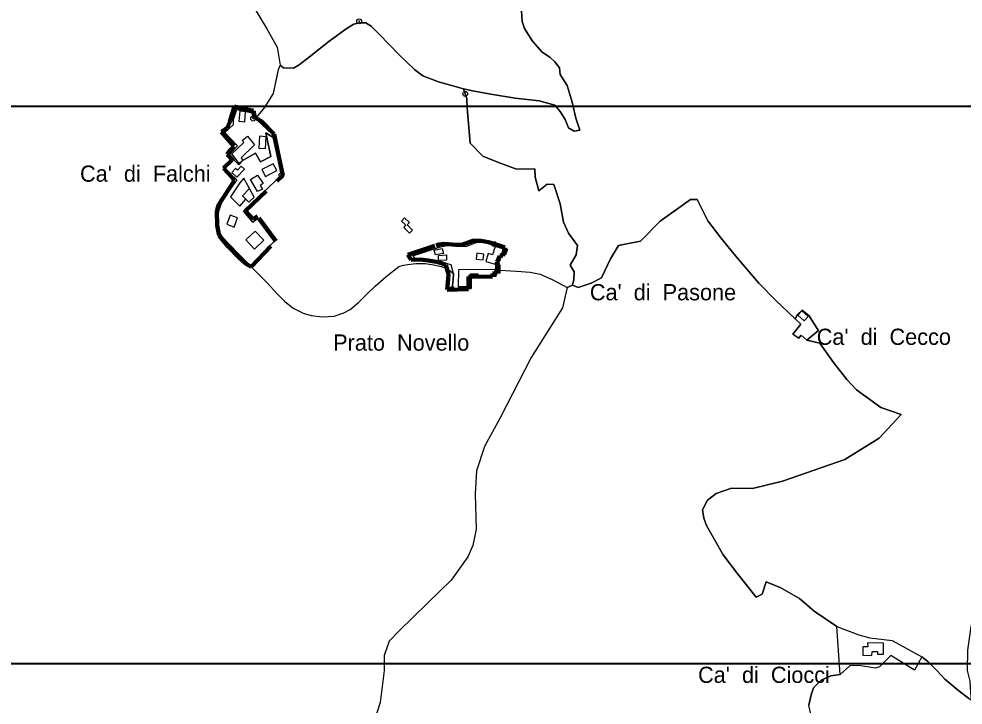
# Model space of a CAD drawing. Extents: x 645880 to 658994, y 884400 to 894744.
# Drawn here: x 652403 to 653394, y 888960 to 889680 of the extents above; entities that cross this region are included whole.
import ezdxf
from ezdxf.enums import TextEntityAlignment as Align

# ---------------------------------------------------------------- set-up
doc = ezdxf.new("R2010")
doc.units = 0
doc.header["$LTSCALE"] = 10
doc.header["$PDMODE"] = 32
doc.header["$PDSIZE"] = 5
doc.linetypes.add('MEDIUM_DASHED', pattern=[4.5, 3, -1.5])
for name, color, linetype, lineweight in [('1', 7, 'Continuous', 25), ('15', 7, 'MEDIUM_DASHED', 100), ('17', 7, 'Continuous', 25), ('18', 7, 'Continuous', 25), ('2', 7, 'Continuous', 25), ('4', 7, 'Continuous', 25), ('6', 7, 'Continuous', 25), ('62', 7, 'Continuous', 35), ('63', 7, 'Continuous', 35), ('7', 7, 'Continuous', 25), ('8', 7, 'Continuous', 25)]:
    doc.layers.add(name, color=color, linetype=linetype, lineweight=lineweight)
doc.layers.add('60', color=7, linetype='Continuous')

msp = doc.modelspace()

# ---------------------------------------------------------------- linework, layer by layer
at = {"layer": '1'}
for points in [[(652858.95, 889412.63), (652856.49, 889421.71), (652853.93, 889422.65), (652847.38, 889424.7), (652839.18, 889426.87), (652829.46, 889428.08), (652819.38, 889428.08), (652816.39, 889431.38), (652844.32, 889440.3), (652851.77, 889442.15), (652864.95, 889441.48), (652871.89, 889441.14), (652883.73, 889445.5), (652890.91, 889445.51), (652901.65, 889443.54)], [(652901.65, 889443.54), (652909.07, 889440.08), (652915.62, 889438.33), (652913.47, 889432.13), (652909.69, 889432.71), (652906.66, 889423.99), (652907.74, 889421.06)], [(652907.74, 889421.06), (652907.78, 889416.09), (652907.76, 889412.93), (652903.09, 889413.24), (652903.37, 889409.66), (652877.57, 889410.31), (652877.65, 889396.95), (652857.6, 889396.39)], [(652857.6, 889396.39), (652858.57, 889406.67), (652858.95, 889412.63)]]:
    msp.add_lwpolyline(points, dxfattribs=at)
for points in [[(652847.26, 889438.79), (652848.65, 889433.74), (652840.32, 889432.39), (652838.94, 889437.1)], [(652895.31, 889433.55), (652892.92, 889425.34), (652905.35, 889421.79), (652908.78, 889433.75), (652913.67, 889432.5), (652915.07, 889437.1), (652902.81, 889441.1), (652899.82, 889432.24)], [(652843.5, 889431.77), (652851.63, 889432.15), (652851.84, 889426.67), (652843.39, 889426.45)], [(652890.86, 889432.86), (652883.47, 889433.97), (652882.84, 889427.67), (652890.23, 889426.94)], [(652864.25, 889398.74), (652864.49, 889416.84), (652902.47, 889417.17), (652902.41, 889410.66), (652885.06, 889410.66), (652885.05, 889411.93), (652876.55, 889411.93), (652876.39, 889398.58)]]:
    msp.add_lwpolyline(points, close=True, dxfattribs=at)
for p in [(652901.65, 889443.54), (652857.6, 889396.39)]:
    msp.add_point(p, dxfattribs=at)
at = {"layer": '15'}
for points in [[(652615.75, 889561.15), (652628.62, 889546.19), (652625.49, 889542.71), (652621.66, 889537.49), (652626.89, 889531.86), (652617.68, 889523.26), (652627.35, 889513.02), (652629.14, 889510.36), (652613.02, 889485.15), (652610.93, 889478.21), (652611.13, 889463.06), (652613.38, 889452.42), (652622.59, 889440.95), (652634.46, 889428.87), (652640.8, 889423.35), (652646.74, 889419.66), (652672.79, 889446.66), (652653.45, 889472.83), (652648.79, 889469.63), (652640.9, 889478.51), (652679.89, 889515.48), (652674.55, 889541.7), (652671.05, 889558.72), (652657.84, 889572.29), (652650.53, 889576.46), (652649.14, 889583.42), (652629.32, 889587.95)], [(652629.32, 889587.95), (652626.88, 889579.94), (652624.42, 889571.91), (652621.64, 889565.6), (652615.75, 889561.15)]]:
    msp.add_lwpolyline(points, dxfattribs=at)
msp.add_lwpolyline([(652853.85, 889412.05), (652851.15, 889421.42), (652849.15, 889422.68), (652842.97, 889424.44), (652832.59, 889426.49), (652824.57, 889427.5), (652814.68, 889427.12), (652811.18, 889432.24), (652840.83, 889442.1), (652843.63, 889442.96), (652848.83, 889443.97), (652853.65, 889443.54), (652861.5, 889442.93), (652867.64, 889442.8), (652880.39, 889447.31), (652888.26, 889447.12), (652895.76, 889445.43), (652907.95, 889441.68), (652913.01, 889439.99), (652910.88, 889430.94), (652907.27, 889431.09), (652904.45, 889424.81), (652904.98, 889420.95), (652904.85, 889412.92), (652900.07, 889412.61), (652899.92, 889409.08), (652874.77, 889409.61), (652874.77, 889396.29), (652852.49, 889395.74), (652852.78, 889399.31), (652853.47, 889407.11)], close=True, dxfattribs=at)
at = {"layer": '17'}
for points in [[(652871.38, 889601.15), (652869.68, 889606.46), (652869.69, 889606.47), (652869.68, 889606.47), (652843.41, 889613.68), (652827.05, 889619.99), (652818.65, 889626.15), (652801.55, 889642.43), (652781.13, 889663.7), (652772.57, 889672.11), (652767.02, 889675.72), (652760.42, 889675.72), (652754.56, 889674.21), (652746.46, 889669.26), (652728.3, 889655.89), (652708.03, 889639.82)], [(652708.03, 889639.82), (652697.08, 889631.56), (652691.07, 889628.11), (652680.87, 889628.56), (652677.13, 889631.26), (652675.18, 889626.47), (652674.2, 889621.82)], [(652674.2, 889621.82), (652669.91, 889601.42), (652660.54, 889586.47), (652651.98, 889576.46), (652653, 889573.44), (652668.8, 889558.95), (652669.92, 889555.18), (652678.53, 889515.99), (652638.67, 889478.15), (652648.7, 889466.42), (652653.59, 889470.35), (652671.65, 889446.86), (652649.47, 889424.75)], [(652983.82, 889400.47), (652985.34, 889406.55), (652985.79, 889414.56), (652981.36, 889421.53), (652987.69, 889432.29), (652989.12, 889441.95), (652979.78, 889455.1), (652974.37, 889466.51), (652970.99, 889485.94), (652964.24, 889506.2), (652957.46, 889506.25), (652948.44, 889499.28), (652944.84, 889513.81), (652944.48, 889522.4), (652925.33, 889522.24), (652906.34, 889529.05), (652890, 889535.76), (652876.43, 889549.32), (652873.26, 889586.38), (652873.12, 889595.73), (652871.38, 889601.15)], [(652819.38, 889428.08), (652816.39, 889431.38), (652844.32, 889440.3), (652851.77, 889442.15), (652864.95, 889441.48), (652871.89, 889441.14), (652883.73, 889445.5), (652890.9, 889445.5), (652901.65, 889443.54), (652909.07, 889440.08), (652915.62, 889438.33), (652913.47, 889432.13), (652909.17, 889433.44), (652906.66, 889423.99), (652907.75, 889421.07), (652907.74, 889421.06), (652907.78, 889416.09), (652925.28, 889415.2), (652939.56, 889414.27), (652949.86, 889412.16), (652963.2, 889406.07), (652978.31, 889398.07), (652983.82, 889400.47)], [(652858.95, 889412.63), (652856.49, 889421.71), (652853.93, 889422.65), (652847.38, 889424.7), (652839.18, 889426.87), (652829.46, 889428.08), (652819.38, 889428.08)], [(652649.47, 889424.75), (652645.94, 889420.69), (652649.89, 889416.69), (652663.41, 889403), (652673.71, 889391.69), (652681.77, 889383.55), (652690.87, 889376.23), (652701.18, 889371.17), (652709.89, 889368.65), (652721.31, 889367.3), (652733.88, 889368.07), (652743.94, 889371.56), (652750.52, 889375.04), (652759.23, 889382.21), (652768.52, 889391.31), (652777.03, 889399.44), (652788.24, 889409.11), (652796.85, 889416.33), (652801.74, 889420.17), (652806.63, 889421.53), (652811.05, 889422.2), (652819.66, 889423.11), (652829.2, 889423.11), (652838.28, 889421.98), (652845.96, 889419.95), (652852.47, 889417.91), (652858.95, 889412.63)]]:
    msp.add_lwpolyline(points, dxfattribs=at)
msp.add_point((652871.38, 889601.15), dxfattribs=at)
at = {"layer": '18'}
for points in [[(652650.6, 889690.43), (652663.31, 889669.23), (652673.91, 889650.15), (652677.13, 889631.26)], [(652650.6, 889690.43), (652663.31, 889669.23), (652673.91, 889650.15), (652677.13, 889631.26)], [(652930.34, 889688.25), (652931.1, 889676.92), (652933.45, 889669.69), (652942.07, 889656.52), (652952.06, 889644.7), (652960.23, 889639.71), (652965.23, 889634.71), (652970.22, 889628.35), (652971.13, 889621.53), (652978.39, 889609.72), (652983.39, 889592.46), (652987.47, 889575.65), (652991.56, 889562.93), (652985.66, 889562.02), (652979.75, 889565.65), (652976.12, 889574.29), (652971.13, 889582.46), (652965.23, 889589.28), (652948.88, 889593.82), (652923.91, 889596.55), (652898.11, 889600.63), (652880.79, 889603.82), (652869.68, 889606.47), (652873.12, 889595.73)], [(652931.1, 889676.92), (652930.34, 889688.25)], [(652691.07, 889628.11), (652697.08, 889631.56), (652708.03, 889639.82), (652728.3, 889655.89), (652746.46, 889669.26), (652754.56, 889674.21), (652760.42, 889675.72), (652767.02, 889675.72), (652772.57, 889672.11), (652781.13, 889663.7), (652801.55, 889642.43), (652818.65, 889626.15), (652827.05, 889619.99), (652843.41, 889613.68), (652869.68, 889606.47)], [(652869.68, 889606.47), (652880.79, 889603.82), (652898.11, 889600.63), (652923.91, 889596.55), (652948.88, 889593.82), (652965.23, 889589.28), (652971.13, 889582.46), (652976.12, 889574.29), (652979.75, 889565.65), (652985.66, 889562.02), (652991.56, 889562.93), (652987.47, 889575.65), (652983.39, 889592.46), (652978.39, 889609.72), (652971.13, 889621.53), (652970.22, 889628.35), (652965.23, 889634.71), (652960.23, 889639.71), (652952.06, 889644.7), (652942.07, 889656.52), (652933.45, 889669.69), (652931.1, 889676.92)], [(652677.13, 889631.26), (652675.18, 889626.47), (652669.91, 889601.42), (652660.54, 889586.47), (652651.98, 889576.46)], [(652677.13, 889631.26), (652680.87, 889628.56), (652691.07, 889628.11)], [(652873.12, 889595.73), (652873.26, 889586.38), (652876.43, 889549.33), (652890, 889535.76), (652906.34, 889529.05), (652925.33, 889522.24), (652944.48, 889522.4), (652944.84, 889513.81), (652948.44, 889499.28), (652957.46, 889506.25), (652964.24, 889506.2), (652970.99, 889485.94), (652974.37, 889466.51), (652979.78, 889455.1), (652989.11, 889441.96)], [(652631.56, 889584.54), (652627.98, 889573.82), (652627.95, 889568.57), (652619.04, 889560.52), (652632.31, 889546.71), (652624.22, 889537.49), (652628.21, 889532.53), (652619.05, 889522.88), (652631.67, 889510.78), (652620.54, 889495.05), (652615.42, 889486.01), (652612.39, 889477.89), (652611.93, 889472.69), (652612.02, 889465.91), (652612.19, 889460.84), (652613.54, 889455.6), (652616.08, 889451.54), (652633.49, 889433.27), (652649.89, 889416.69), (652663.41, 889403), (652673.71, 889391.69), (652681.77, 889383.55), (652690.87, 889376.23), (652701.18, 889371.17), (652709.89, 889368.65), (652721.31, 889367.3), (652733.88, 889368.07), (652743.94, 889371.56), (652750.52, 889375.04), (652759.23, 889382.21), (652768.52, 889391.31), (652777.03, 889399.44), (652788.24, 889409.11), (652796.85, 889416.33), (652801.74, 889420.17), (652806.63, 889421.53), (652811.05, 889422.2), (652819.66, 889423.11), (652829.2, 889423.11), (652838.28, 889421.98)], [(652651.98, 889576.46), (652653, 889573.44), (652648.86, 889575.13), (652647.73, 889580.97), (652631.56, 889584.54)], [(653217.59, 889365.17), (653196.77, 889384.59), (653179.47, 889402.62), (653154.91, 889431.3), (653139.57, 889450.19), (653126.01, 889467.89), (653118.93, 889481.95), (653114.8, 889490.32), (653107.55, 889490.5), (653076.02, 889467.69), (653055.1, 889446.76), (653039.18, 889443.64), (653032, 889442.07), (653023.88, 889428.02), (653014.2, 889408.33), (653003.58, 889402.71), (652989.85, 889398.02), (652983.82, 889400.47), (652978.31, 889398.07)], [(652983.82, 889400.47), (652989.85, 889398.02), (653003.58, 889402.71), (653014.2, 889408.33), (653023.88, 889428.02), (653032, 889442.07), (653039.18, 889443.64), (653055.1, 889446.76), (653076.02, 889467.69), (653107.55, 889490.5), (653114.8, 889490.32), (653118.93, 889481.95), (653126.01, 889467.89), (653139.57, 889450.19), (653154.91, 889431.3), (653179.47, 889402.62), (653196.77, 889384.59), (653217.59, 889365.17), (653220.09, 889369.68), (653224.84, 889374.43), (653232.34, 889368.43), (653236.59, 889360.92), (653241.84, 889352.92), (653229.84, 889342.91)], [(652989.11, 889441.96), (652987.69, 889432.3), (652981.36, 889421.53)], [(652838.28, 889421.98), (652845.96, 889419.95), (652852.47, 889417.91), (652858.95, 889412.63), (652858.98, 889412.66), (652858.6, 889406.7), (652857.6, 889396.39), (652877.68, 889396.98), (652877.57, 889410.31), (652903.37, 889409.66), (652903.11, 889413.26), (652907.77, 889412.94), (652907.78, 889416.09), (652925.28, 889415.2), (652939.56, 889414.27), (652949.86, 889412.16), (652963.2, 889406.07), (652978.31, 889398.07)], [(652981.36, 889421.53), (652985.79, 889414.56), (652985.34, 889406.55), (652983.82, 889400.47)], [(652978.31, 889398.07), (652973.42, 889376.81), (652940.71, 889324.58), (652907.98, 889261.28), (652891.63, 889231.43), (652883.21, 889205.91), (652881.74, 889181.69), (652882.78, 889144.61), (652879.18, 889127.37), (652873.98, 889115.41), (652856.76, 889091.14), (652832.29, 889067.24), (652801.75, 889037.73), (652791.74, 889027.29), (652786.16, 889011.99), (652786.16, 888996.46), (652782.28, 888962.96), (652774.7, 888940.15)], [(652978.31, 889398.07), (652973.42, 889376.81), (652940.71, 889324.58), (652907.98, 889261.28), (652891.63, 889231.43), (652883.21, 889205.91), (652881.74, 889181.69), (652882.78, 889144.61), (652879.18, 889127.37), (652873.98, 889115.41), (652856.76, 889091.14), (652832.29, 889067.24), (652801.75, 889037.73), (652791.74, 889027.29), (652786.16, 889011.99), (652786.16, 888996.46), (652782.28, 888962.96), (652774.7, 888940.15)], [(653261.39, 889042.67), (653237.39, 889058.52), (653222.01, 889071.99), (653202.47, 889082.89), (653187.09, 889089.3), (653182.93, 889076.48), (653176.52, 889073.27), (653156.22, 889098.76), (653141.91, 889117.52), (653124.63, 889148.29), (653121.81, 889156.06), (653120.45, 889164.98), (653125.57, 889174.92), (653134.54, 889181.97), (653150.57, 889187.74), (653172.67, 889187.1), (653204.07, 889194.8), (653269.76, 889217.56), (653305.76, 889239.97), (653328.7, 889265.01), (653307.24, 889272.07), (653281.92, 889290.66), (653271.67, 889301.57), (653257.57, 889319.52), (653243.47, 889339.72), (653229.84, 889342.91), (653223.84, 889347.91), (653221.34, 889344.91), (653215.09, 889348.92), (653223.59, 889359.42), (653217.59, 889365.17)], [(653229.84, 889342.91), (653243.47, 889339.72), (653257.57, 889319.52), (653271.67, 889301.57), (653281.92, 889290.66), (653307.24, 889272.07), (653328.7, 889265.01), (653305.76, 889239.97), (653269.76, 889217.56), (653204.07, 889194.8), (653172.67, 889187.1), (653150.57, 889187.74), (653134.54, 889181.97), (653125.57, 889174.92), (653120.45, 889164.98), (653121.81, 889156.06), (653124.63, 889148.29), (653141.91, 889117.52), (653156.22, 889098.76), (653176.52, 889073.27), (653182.93, 889076.48), (653187.09, 889089.3), (653202.47, 889082.89), (653222.01, 889071.99), (653237.39, 889058.52), (653261.39, 889042.67), (653284.38, 889033.66), (653295.88, 889030.66), (653319.38, 889027.66), (653350.37, 889010.65)], [(653350.37, 889010.65), (653356.67, 889005.77), (653366.05, 888996.39), (653374.64, 888987.27), (653389.22, 888975.03), (653399.38, 888967.21), (653403.35, 888965), (653402.17, 888968.15), (653400.99, 888985.09), (653398.24, 888996.52), (653398.63, 889017.79), (653402.17, 889042.22), (653407.68, 889065.47), (653518.66, 889104.08)], [(653240.43, 888894.67), (653240.23, 888905.02), (653238.13, 888923.29), (653235.32, 888935.24), (653234.19, 888948.86), (653231.81, 888959.85), (653234.19, 888970.98), (653236.72, 888978.13), (653244.76, 888986.05), (653254.99, 888990.78), (653264.89, 888992.14), (653261.39, 889042.67)], [(653350.37, 889010.65), (653342.87, 888996.64), (653317.88, 889012.15), (653305.88, 889000.14), (653301.38, 888998.64), (653284.38, 889001.64), (653274.89, 889001.14), (653264.89, 888992.14)], [(653399.37, 888967.21), (653389.22, 888975.03), (653374.64, 888987.27), (653366.05, 888996.39), (653356.67, 889005.77), (653350.37, 889010.65)], [(653264.89, 888992.14), (653254.99, 888990.78), (653244.76, 888986.05), (653236.72, 888978.13), (653234.19, 888970.98), (653231.81, 888959.85)]]:
    msp.add_lwpolyline(points, dxfattribs=at)
msp.add_point((652760.12, 889677.2), dxfattribs=at)
at = {"layer": '2'}
for points in [[(652631.56, 889584.54), (652627.98, 889573.82), (652627.95, 889568.57)], [(652648.86, 889575.13), (652647.73, 889580.97), (652631.56, 889584.54)], [(652662.21, 889560.08), (652669.92, 889555.18), (652668.8, 889558.95), (652653, 889573.44), (652648.86, 889575.13)], [(652627.95, 889568.57), (652619.04, 889560.52), (652632.31, 889546.71), (652624.22, 889537.49), (652628.88, 889531.7), (652633.69, 889526.77), (652638.49, 889531.47), (652651.49, 889538.81), (652656.57, 889529.96)], [(652656.57, 889529.96), (652667.29, 889535.42), (652662.21, 889560.08)]]:
    msp.add_lwpolyline(points, dxfattribs=at)
for points in [[(652626.48, 889538.05), (652639.27, 889550.1), (652637.76, 889552.55), (652642.84, 889556.69), (652650.18, 889547.65), (652636.45, 889533.91), (652637.95, 889531.28), (652634.19, 889528.08)], [(652646.23, 889511.33), (652653.56, 889515.84), (652659.39, 889507), (652656.2, 889505.12), (652658.64, 889501.16), (652653.56, 889498.72)], [(653261.39, 889042.67), (653284.38, 889033.66), (653295.88, 889030.66), (653319.38, 889027.66), (653350.37, 889010.65), (653342.87, 888996.64), (653317.88, 889012.15), (653305.88, 889000.14), (653301.38, 888998.64), (653284.38, 889001.64), (653274.89, 889001.14), (653264.89, 888992.14)], [(653288.42, 889021.29), (653288.52, 889012.34), (653297.9, 889012.24), (653298.22, 889016.44), (653303.93, 889016.33), (653304.04, 889013.42), (653310.07, 889013.53), (653310.18, 889024.85), (653293.48, 889025.39), (653293.7, 889021.29)]]:
    msp.add_lwpolyline(points, close=True, dxfattribs=at)
msp.add_point((652648.86, 889575.13), dxfattribs=at)
at = {"layer": '4'}
for points in [[(653224.84, 889374.43), (653220.09, 889369.68), (653217.59, 889365.17), (653223.59, 889359.42), (653215.09, 889348.92), (653221.34, 889344.91), (653223.84, 889347.91), (653229.84, 889342.91), (653241.84, 889352.92), (653236.59, 889360.92), (653232.34, 889368.43)], [(653220.47, 889369.14), (653224.37, 889373.46), (653231.02, 889367.66), (653227.01, 889363.22)]]:
    msp.add_lwpolyline(points, close=True, dxfattribs=at)
at = {"layer": '6'}
msp.add_lwpolyline([(652806.79, 889460.98), (652813.01, 889455.07), (652816.17, 889458.23), (652810.42, 889463.64), (652812.89, 889466.3), (652807.72, 889471.17), (652804.49, 889467.75), (652808.88, 889463.61)], close=True, dxfattribs=at)
at = {"layer": '62', "lineweight": 40}
msp.add_lwpolyline([(650022.35, 889003.81), (658994.16, 889003.81), (658994.16, 894743.81), (650022.35, 894743.81)], close=True, dxfattribs=at)
msp.add_lwpolyline([(650022.35, 889003.81), (658994.16, 889003.81), (658994.16, 894743.81), (650022.35, 894743.81)], close=True, dxfattribs=at)
at = {"layer": '63', "lineweight": 40}
msp.add_lwpolyline([(656397.82, 884399.72), (650080.32, 884399.72), (650080.32, 889588.16), (656397.82, 889588.16)], close=True, dxfattribs=at)
at = {"layer": '7'}
for points in [[(652633.96, 889572.38), (652640.13, 889571.88), (652640.98, 889582.31), (652634.81, 889582.81)], [(652655.55, 889556.62), (652654.78, 889544.14), (652661.7, 889543.71), (652662.47, 889556.19)], [(652626.47, 889518.59), (652631.87, 889513.6), (652639.76, 889522.14), (652636.29, 889525.35), (652632.37, 889521.11), (652630.44, 889522.89)], [(652658.14, 889521.65), (652662, 889514.41), (652673.68, 889520.63), (652669.83, 889527.87)], [(652634.83, 889507.75), (652625.21, 889493.08), (652634.73, 889483.35), (652641.16, 889490.84), (652644.51, 889487.59), (652649.91, 889492.83), (652639.1, 889512.8)], [(652624.87, 889474.06), (652621.36, 889464.5), (652629.09, 889461.48), (652632.4, 889471.24)], [(652650.93, 889457.17), (652641.16, 889447.94), (652650.28, 889438.28), (652660.05, 889447.51)]]:
    msp.add_lwpolyline(points, close=True, dxfattribs=at)
msp.add_lwpolyline([(652641.16, 889490.84), (652637.73, 889494.17), (652645.08, 889501.75)], dxfattribs=at)
at = {"layer": '8'}
for points in [[(652662.21, 889560.08), (652667.29, 889535.42), (652656.57, 889529.96), (652651.49, 889538.81), (652638.49, 889531.47), (652633.69, 889526.77), (652628.88, 889531.7), (652628.21, 889532.53)], [(652678.53, 889515.99), (652669.92, 889555.18), (652662.21, 889560.08)], [(652628.21, 889532.53), (652619.05, 889522.88), (652631.67, 889510.78), (652620.54, 889495.05), (652615.42, 889486.01), (652612.39, 889477.89), (652611.93, 889472.69), (652612.02, 889465.91), (652612.19, 889460.84), (652613.54, 889455.6), (652616.08, 889451.54), (652633.49, 889433.27), (652645.67, 889420.96), (652645.8, 889420.53), (652649.47, 889424.75), (652671.65, 889446.86), (652653.59, 889470.35), (652648.7, 889466.42), (652638.67, 889478.15), (652678.53, 889515.99)]]:
    msp.add_lwpolyline(points, dxfattribs=at)
msp.add_point((652678.53, 889515.99), dxfattribs=at)

# ---------------------------------------------------------------- texts
at = {"layer": '60'}
for s, p in [("Ca'  di  Falchi", (652535.74, 889508.95)), ("Ca'  di  Pasone", (653078.86, 889384.6)), ('Prato  Novello', (652804.23, 889331.8)), ("Ca'  di  Cecco", (653310.53, 889337.86)), ("Ca'  di  Ciocci", (653184.79, 888983.34))]:
    msp.add_text(s, height=17, dxfattribs=at).set_placement(p, align=Align.CENTER)

doc.saveas('drawing.dxf')
